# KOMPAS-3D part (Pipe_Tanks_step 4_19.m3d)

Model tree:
1. X Axis
2. Y Axis
3. Z Axis  (labels: Bend 90 Dn 20; Pipe Dn 20)
     Òîëùèíà ñòåíêè 1 = 1

Referenced files in C:\Documents and Settings\kashirsky\Мои документы\Camtasia Studio\Pipelines3D\Tanks\: Tanks_step 4.a3d
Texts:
  Pipe Dn 50
  Steel ASTM A295
  Three Point Plane
  Plane at Angle
  Line and Point Plane
  Axis through Two Vertices
  Axis of Feature
  Axis of Conical Surface
  Axis through Edge
  Trim by Surface
  Trim by Sketch
  Feature with No History
  Intersection Axis of Two Planes
  Two Line Plane
  Line and Face Plane
  Bend by line
  Hole in sheet body
  Cut in sheet body
  Point in CM
  Linear Dimension from Line to Point
  Surface Finish Symbol
  Geometric Tolerance Symbol
  Leader #1
  Leader #2
  Leader #3
  Shape Deviations and Datum
  Node point number
  Mark of coordination axis
  Node point designation
  Mark/Reference designation with leader
  Mark/reference designation on line
  Mark/Reference designation without leader
  Bend 90 Dn 20
  Pipe Dn 20
  Plane of section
